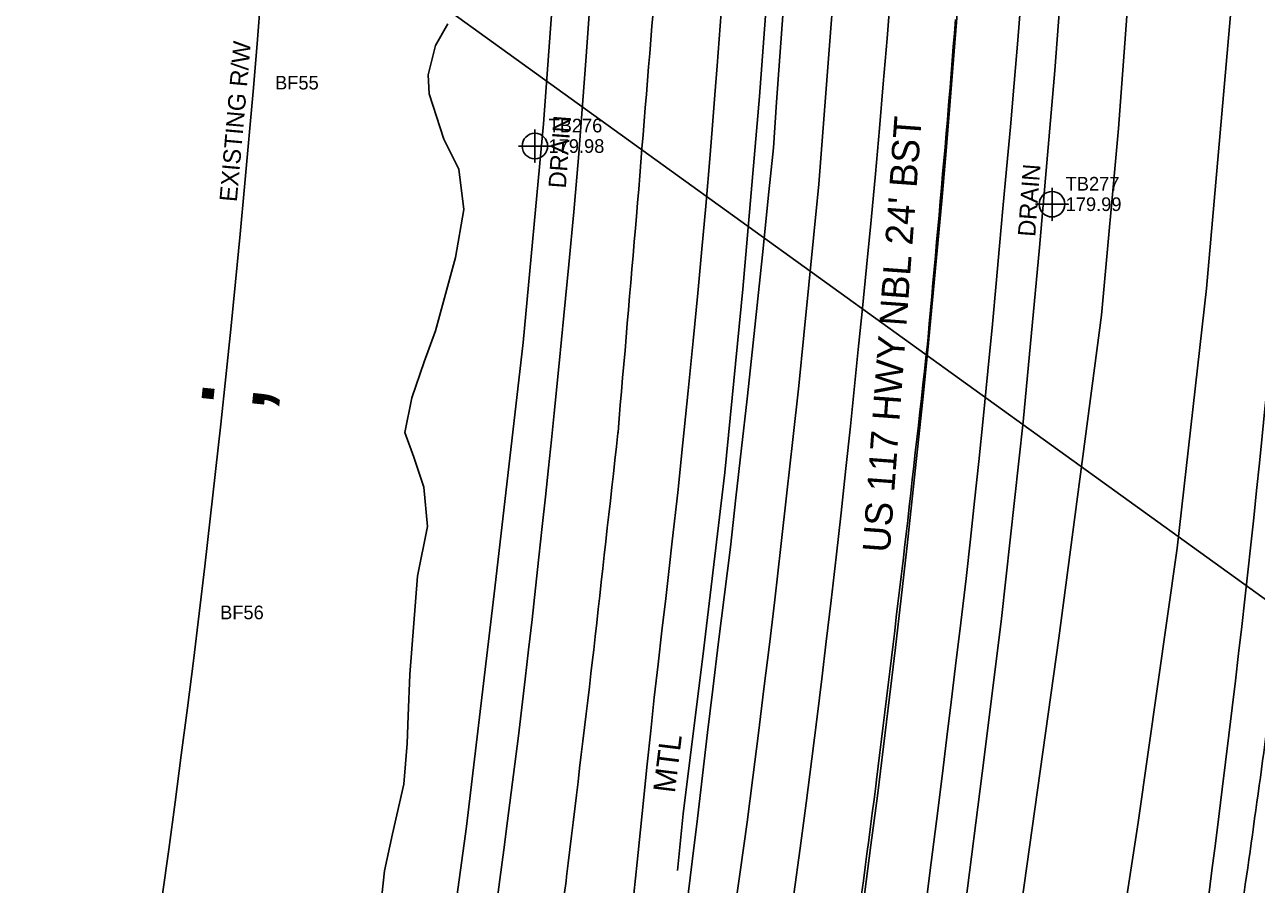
# Model space of a CAD drawing. Extents: x 2262665 to 2270527, y 505476 to 514960.
# Drawn here: x 2266138.9 to 2266364.6, y 509978.6 to 510136.1 of the extents above; entities that cross this region are included whole.
import ezdxf

# ---------------------------------------------------------------- set-up
doc = ezdxf.new("R2010")
doc.units = 0
for name, color, linetype in [('Exist Boundary City Limits', 7, 'Continuous'), ('Exist Guardrail', 7, 'Continuous'), ('Exist Guardrail Text', 7, 'Continuous'), ('Exist Horizontal Alignment', 7, 'Continuous'), ('Exist Property Corner Cogo Number', 7, 'Continuous'), ('Exist Right of Way Control of Access CA Symbol CELL', 7, 'Continuous'), ('Exist Right of Way Control of Access Line', 7, 'Continuous'), ('Exist Right of Way Line Text', 7, 'Continuous'), ('Exist Roads EOP', 7, 'Continuous'), ('Exist Roads EOP Text', 7, 'Continuous'), ('Exist Roads EOT', 7, 'Continuous'), ('Exist Structure Minor Drop Inlet Cogo Elevation', 7, 'Continuous'), ('Exist Structure Minor Drop Inlet Cogo Number', 7, 'Continuous'), ('Exist Structure Minor Drop Inlet Cogo Point CELL', 7, 'Continuous'), ('Exist Structure Minor Drop Inlet Text', 7, 'Continuous'), ('Exist Structure Minor Paved Ditch or Gutter', 7, 'Continuous'), ('Exist Vegetation Hedge Row', 7, 'Continuous'), ('Exist Vegetation Woods Line', 7, 'Continuous'), ('Scratch_Level_1', 7, 'Continuous')]:
    doc.layers.add(name, color=color, linetype=linetype)

msp = doc.modelspace()

# ---------------------------------------------------------------- linework, layer by layer
at = {"layer": 'Exist Boundary City Limits'}
msp.add_lwpolyline([(2266245.96, 514959.69), (2263948.01, 511776.47), (2268229.07, 508686.01), (2270527.02, 511869.23)], dxfattribs=at)
at = {"layer": 'Exist Guardrail'}
for points in [[(2266160.84, 509676.92), (2266165.08, 509693.72), (2266174.04, 509733.83), (2266182.53, 509771.8), (2266190.31, 509809.74), (2266198.21, 509851.61), (2266206.26, 509898.03), (2266214.05, 509947), (2266219.83, 509989.18), (2266225.03, 510032.89), (2266230.21, 510077.92), (2266233.96, 510117.98), (2266237.41, 510165.42), (2266240.43, 510208.57), (2266242.31, 510234.33)], [(2266334.39, 510233.28), (2266333.37, 510212.85), (2266331.81, 510184.43), (2266330.09, 510160.21), (2266327.64, 510127.74), (2266324.86, 510095.33), (2266321.82, 510063.37), (2266317.9, 510027.29), (2266314.72, 510001.82), (2266310.83, 509971.64), (2266306.61, 509940.64), (2266302.52, 509912.93), (2266297.99, 509884.97), (2266292.86, 509854.22), (2266287.18, 509821.48), (2266279.3, 509783.63), (2266270.08, 509740.16), (2266261.99, 509703.88), (2266253.35, 509666.68), (2266250.16, 509652.66)], [(2266280.79, 510232.67), (2266278.81, 510198.94), (2266276.08, 510157.53), (2266273.52, 510122.95), (2266270.47, 510087.64), (2266267.19, 510054.09), (2266263.33, 510021.87), (2266259.56, 509991.5), (2266258.49, 509981.14)]]:
    msp.add_lwpolyline(points, dxfattribs=at)
at = {"layer": 'Exist Horizontal Alignment'}
for centre, radius, start, end in [((2263773.45, 510337.89), 2625, 349.59137, 358.85635), ((2263436.25, 510359.19), 2882, 309.60499, 355.6461)]:
    msp.add_arc(centre, radius, start, end, dxfattribs=at)
at = {"layer": 'Exist Right of Way Control of Access CA Symbol CELL'}
msp.add_line((2266175.89, 510072.92), (2266175.89, 510072.92), dxfattribs=at)
at = {"layer": 'Exist Right of Way Control of Access Line'}
msp.add_arc((2263436.25, 510359.19), 2754.56, 309.60499, 355.6461, dxfattribs=at)
at = {"layer": 'Exist Roads EOP'}
for points in [[(2266279.81, 509976.82), (2266280.96, 509985.2), (2266282.07, 509993.46), (2266283.13, 510001.6), (2266284.1, 510009.31), (2266284.94, 510016.25), (2266285.76, 510023.13), (2266286.66, 510030.64), (2266287.59, 510038.57), (2266288.48, 510046.71), (2266289.35, 510054.81), (2266290.18, 510062.59), (2266290.95, 510069.91), (2266291.64, 510076.62), (2266292.34, 510083.59), (2266293.14, 510091.71), (2266293.97, 510100.33), (2266294.77, 510108.8), (2266295.52, 510117.12), (2266296.22, 510125.3), (2266296.9, 510133.63), (2266297.61, 510142.42)], [(2266242.46, 510139.78), (2266241.75, 510130.28), (2266241.08, 510121.42), (2266240.34, 510111.76), (2266239.53, 510101.84), (2266238.62, 510092.18), (2266237.7, 510082.87), (2266236.82, 510074.02), (2266235.9, 510064.94), (2266235.4, 510060.05), (2266234.87, 510054.93), (2266234.32, 510049.62), (2266233.74, 510044.17), (2266233.13, 510038.58), (2266232.5, 510032.85), (2266231.86, 510027.13), (2266231.22, 510021.58), (2266230.6, 510016.2), (2266229.98, 510010.98), (2266229.36, 510005.83), (2266228.72, 510000.65), (2266228.06, 509995.46), (2266227.39, 509990.23), (2266226.7, 509984.92), (2266225.97, 509979.46), (2266225.22, 509973.86)], [(2266321.47, 510141.13), (2266320.87, 510133.32), (2266320.22, 510125.44), (2266319.51, 510117.41), (2266318.8, 510109.63), (2266318.13, 510102.47), (2266317.5, 510095.62), (2266316.89, 510088.71), (2266316.22, 510081.23), (2266315.4, 510072.63), (2266314.53, 510063.92), (2266313.7, 510056.07), (2266312.92, 510048.81), (2266312.17, 510041.87), (2266311.37, 510034.65), (2266310.42, 510026.54), (2266309.46, 510018.63), (2266308.65, 510011.98), (2266307.87, 510005.58), (2266306.98, 509998.4), (2266305.96, 509990.19), (2266304.76, 509980.71), (2266303.5, 509970.88)], [(2266266.51, 510138.37), (2266265.78, 510128.59), (2266265.38, 510123.3), (2266264.94, 510117.74), (2266264.5, 510112.29), (2266263.71, 510102.85), (2266262.99, 510095.03), (2266262.22, 510086.92), (2266261.37, 510078.21), (2266260.46, 510069.04), (2266259.5, 510059.52), (2266258.54, 510050.39), (2266257.55, 510041.46), (2266256.98, 510036.46), (2266256.35, 510031), (2266255.66, 510025.08), (2266254.95, 510018.95), (2266254.26, 510012.82), (2266253.6, 510006.71), (2266252.96, 510000.61), (2266252.33, 509994.56), (2266251.71, 509988.57), (2266251.1, 509982.65), (2266250.5, 509976.8)]]:
    msp.add_lwpolyline(points, dxfattribs=at)
for points in [[(2266387.02, 510213.77), (2266383.96, 510164.13), (2266379.47, 510113.75), (2266374, 510066.49), (2266368.14, 510019.35), (2266361.46, 509971.05), (2266354.23, 509922.66), (2266346.61, 509873.42), (2266339.5, 509830.06)], [(2266405.94, 510212.74), (2266402.45, 510162.89), (2266397.89, 510112.57), (2266392.37, 510064.61), (2266386.2, 510016.82), (2266379.43, 509968.56), (2266372.4, 509918.85), (2266365.25, 509870.66), (2266358.04, 509827.1)]]:
    msp.add_spline(points, degree=3, dxfattribs=at)
at = {"layer": 'Exist Roads EOT'}
for points in [[(2266237.75, 509976.69), (2266238.08, 509979.16), (2266238.2, 509980.03), (2266238.5, 509982.51), (2266238.79, 509985), (2266239.09, 509987.48), (2266239.39, 509989.96), (2266239.69, 509992.44), (2266239.98, 509994.92), (2266240.28, 509997.41), (2266240.58, 509999.89), (2266240.87, 510002.37), (2266241.17, 510004.85), (2266241.47, 510007.33), (2266241.76, 510009.82), (2266242.06, 510012.3), (2266242.36, 510014.78), (2266242.65, 510017.26), (2266242.95, 510019.74), (2266243.17, 510021.55), (2266243.44, 510024.03), (2266243.72, 510026.52), (2266244, 510029), (2266244.27, 510031.49), (2266244.55, 510033.97), (2266244.82, 510036.45), (2266245.1, 510038.94), (2266245.38, 510041.42), (2266245.65, 510043.91), (2266245.93, 510046.39), (2266246.21, 510048.88), (2266246.48, 510051.36), (2266246.76, 510053.85), (2266247.04, 510056.33), (2266247.31, 510058.81), (2266247.59, 510061.3), (2266247.61, 510061.46), (2266247.82, 510063.95), (2266248.03, 510066.44), (2266248.25, 510068.93), (2266248.46, 510071.42), (2266248.67, 510073.91), (2266248.89, 510076.4), (2266249.1, 510078.89), (2266249.31, 510081.38), (2266249.53, 510083.87), (2266249.74, 510086.36), (2266249.95, 510088.85), (2266250.17, 510091.34), (2266250.38, 510093.83), (2266250.59, 510096.33), (2266250.81, 510098.82), (2266250.99, 510100.99), (2266251.19, 510103.48), (2266251.4, 510105.97), (2266251.6, 510108.46), (2266251.8, 510110.95), (2266252, 510113.44), (2266252.21, 510115.93), (2266252.41, 510118.43), (2266252.61, 510120.92), (2266252.81, 510123.41), (2266253.02, 510125.9), (2266253.22, 510128.39), (2266253.42, 510130.88), (2266253.62, 510133.38), (2266253.82, 510135.87), (2266254.03, 510138.36)], [(2266309.44, 510137.07), (2266309.24, 510134.58), (2266309.04, 510132.09), (2266308.84, 510129.6), (2266308.65, 510127.11), (2266308.45, 510124.61), (2266308.25, 510122.12), (2266308.05, 510119.63), (2266307.98, 510118.69), (2266307.76, 510116.2), (2266307.53, 510113.71), (2266307.31, 510111.22), (2266307.09, 510108.73), (2266306.87, 510106.24), (2266306.65, 510103.75), (2266306.43, 510101.26), (2266306.2, 510098.77), (2266305.98, 510096.28), (2266305.76, 510093.79), (2266305.54, 510091.3), (2266305.32, 510088.81), (2266305.1, 510086.32), (2266304.87, 510083.83), (2266304.65, 510081.34), (2266304.43, 510078.85), (2266304.32, 510077.59), (2266304.04, 510075.11), (2266303.76, 510072.62), (2266303.48, 510070.14), (2266303.2, 510067.65), (2266302.92, 510065.17), (2266302.64, 510062.69), (2266302.36, 510060.2), (2266302.08, 510057.72), (2266301.8, 510055.23), (2266301.52, 510052.75), (2266301.25, 510050.26), (2266300.97, 510047.78), (2266300.69, 510045.3), (2266300.41, 510042.81), (2266300.13, 510040.33), (2266299.85, 510037.84), (2266299.81, 510037.48), (2266299.51, 510035), (2266299.2, 510032.52), (2266298.9, 510030.04), (2266298.6, 510027.56), (2266298.3, 510025.07), (2266298, 510022.59), (2266297.7, 510020.11), (2266297.4, 510017.63), (2266297.09, 510015.15), (2266296.79, 510012.67), (2266296.49, 510010.18), (2266296.19, 510007.7), (2266295.89, 510005.22), (2266295.59, 510002.74), (2266295.28, 510000.26), (2266294.98, 509997.78), (2266294.84, 509996.6), (2266294.52, 509994.13), (2266294.19, 509991.65), (2266293.87, 509989.17), (2266293.55, 509986.69), (2266293.22, 509984.21), (2266292.9, 509981.73), (2266292.57, 509979.25), (2266292.25, 509976.77)]]:
    msp.add_lwpolyline(points, dxfattribs=at)
at = {"layer": 'Exist Structure Minor Drop Inlet Cogo Point CELL'}
for points in [[(2266232.38, 510116.9), (2266232.38, 510110.9), (2266232.38, 510113.9), (2266235.38, 510113.9), (2266229.38, 510113.9)], [(2266327.13, 510106.24), (2266327.13, 510100.24), (2266327.13, 510103.24), (2266330.13, 510103.24), (2266324.13, 510103.24)]]:
    msp.add_lwpolyline(points, dxfattribs=at)
for centre in [(2266232.38, 510113.9), (2266327.13, 510103.24)]:
    msp.add_circle(centre, 2.34, dxfattribs=at)
at = {"layer": 'Exist Structure Minor Paved Ditch or Gutter'}
for points in [[(2266287.1, 510141.84), (2266286.43, 510133.11), (2266285.76, 510124.39), (2266285.09, 510115.66), (2266284.43, 510106.94), (2266283.51, 510097.69), (2266282.58, 510088.45), (2266281.66, 510079.21), (2266280.74, 510069.96), (2266279.65, 510060.15), (2266278.55, 510050.34), (2266277.46, 510040.53), (2266276.36, 510030.72), (2266275.35, 510022.58), (2266274.34, 510014.44), (2266273.33, 510006.29), (2266272.31, 509998.15), (2266271.3, 509990.01), (2266269.99, 509980.92), (2266268.68, 509971.83)], [(2266260.15, 509974.32), (2266261.22, 509982.76), (2266262.16, 509990.66), (2266263.1, 509998.55), (2266264.03, 510006.45), (2266264.97, 510014.34), (2266266.05, 510023.02), (2266267.13, 510031.69), (2266268.2, 510040.37), (2266269.22, 510049.44), (2266270.23, 510058.52), (2266271.25, 510067.59), (2266272.27, 510076.67), (2266273.22, 510085.89), (2266274.18, 510095.11), (2266275.13, 510104.33), (2266276.09, 510113.55), (2266276.67, 510121.92), (2266277.26, 510130.29), (2266277.84, 510138.66)]]:
    msp.add_lwpolyline(points, dxfattribs=at)
at = {"layer": 'Exist Vegetation Hedge Row'}
for points in [[(2266367.57, 510230.78), (2266364.19, 510188.93), (2266360.76, 510148.39), (2266355.46, 510087.81), (2266350.09, 510040.2), (2266342.93, 509989.96), (2266335.75, 509943.47)], [(2266319.57, 509961.03), (2266328.36, 510023.72), (2266336.19, 510082.9), (2266339.31, 510117.09), (2266343.75, 510177.27), (2266345.68, 510213.16)]]:
    msp.add_lwpolyline(points, dxfattribs=at)
at = {"layer": 'Exist Vegetation Woods Line'}
msp.add_lwpolyline([(2266216.43, 510136.32), (2266214.16, 510132.35), (2266212.85, 510126.96), (2266212.99, 510123.47), (2266215.72, 510115.14), (2266218.46, 510109.68), (2266219.36, 510102.27), (2266217.84, 510093.5), (2266214.18, 510080.02), (2266212.1, 510074.33), (2266209.85, 510067.78), (2266208.58, 510061.42), (2266210.17, 510056.9), (2266212.01, 510051.39), (2266212.72, 510044.15), (2266210.86, 510035.05), (2266209.45, 510017.04), (2266209.16, 510009.47), (2266208.99, 510004.4), (2266208.34, 509996.94), (2266206.26, 509987.86), (2266204.8, 509981.08), (2266204.32, 509976.55)], dxfattribs=at)
at = {"layer": 'Scratch_Level_1'}
msp.add_arc((2263436.25, 510359.19), 2944.56, 343.16776, 355.6461, dxfattribs=at)

# ---------------------------------------------------------------- texts
at = {"layer": 'Exist Guardrail Text'}
msp.add_text('MTL', height=4, rotation=82.9241, dxfattribs=at).set_placement((2266258.01, 509995.22))
at = {"layer": 'Exist Property Corner Cogo Number'}
for s, p in [('BF55', (2266184.78, 510124.26)), ('BF56', (2266174.71, 510027.18))]:
    msp.add_text(s, height=2.5, dxfattribs=at).set_placement(p)
at = {"layer": 'Exist Right of Way Control of Access CA Symbol CELL'}
msp.add_text(';', height=15, rotation=84.0039, dxfattribs=at).set_placement((2266182.57, 510064.67))
at = {"layer": 'Exist Right of Way Line Text'}
msp.add_text('EXISTING R/W', height=3.2, rotation=84.9581, dxfattribs=at).set_placement((2266177.76, 510103.58))
at = {"layer": 'Exist Roads EOP Text'}
msp.add_text("US 117 HWY NBL 24' BST", height=5, rotation=85.8016, dxfattribs=at).set_placement((2266297.4, 510039.29))
at = {"layer": 'Exist Structure Minor Drop Inlet Cogo Elevation'}
for s, p in [('179.98', (2266234.88, 510112.65)), ('179.99', (2266329.63, 510101.99))]:
    msp.add_text(s, height=2.5, dxfattribs=at).set_placement(p)
at = {"layer": 'Exist Structure Minor Drop Inlet Cogo Number'}
for s, p in [('TB276', (2266234.88, 510116.4)), ('TB277', (2266329.63, 510105.74))]:
    msp.add_text(s, height=2.5, dxfattribs=at).set_placement(p)
at = {"layer": 'Exist Structure Minor Drop Inlet Text'}
for p in [(2266238.04, 510106.07), (2266324.05, 510097.2)]:
    msp.add_text('DRAIN', height=3.2, rotation=85.8017, dxfattribs=at).set_placement(p)

doc.saveas('drawing.dxf')
